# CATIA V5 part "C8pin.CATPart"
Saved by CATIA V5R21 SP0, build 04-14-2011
Part number: C8pin
Bounding box of the stored display mesh (mm): x -12.556 to 12.556, y -12.696 to 12.696, z 0 to 152.4
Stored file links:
  C:\Users\User\Desktop\B.D.M.A\Chapter8\C8pin.CATPart
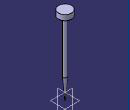
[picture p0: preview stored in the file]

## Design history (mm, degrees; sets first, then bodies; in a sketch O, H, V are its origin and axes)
Body1 (main body)
  Sketch1 on zx-plane, origin (0, 0, 0), H (-1, 0, 0), V (0, 0, 1)
    line L1 (0, 0) -> (3.81, 40.64)
    line L2 (3.81, 40.64) -> (3.81, 142.24)
    line L3 (3.81, 142.24) -> (12.7, 142.24)
    line L4 (12.7, 142.24) -> (12.7, 152.4)
    line L5 (12.7, 152.4) -> (0, 152.4)
    point P5 (0, 152.4)
    axis line L6 (0, 152.4) -> (0, 0)
    length L5 = 12.7
    length L4 = 10.16
    length L2 = 101.6
    distance L6 L2 = 3.81
    distance L5 O = 152.4
    vertical: L2 V, L4 V, L6 V
    horizontal: L3 H, L5 H
    coincidence: P5 V
  Shaft1: profile Sketch1, axis Sketch1.L6, angle 360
